// Mitsubishi GX Works2 project: 28.开根指令   PLC: FX3U/FX3UC

PROGRAM MAIN
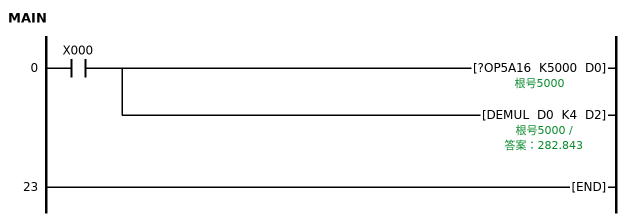
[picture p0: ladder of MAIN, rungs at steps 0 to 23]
0     LD      X000
      ?OP5A16 K5000 D0  ; 根号5000
        [note] 浮点运算加DE。SQR开平方根
      DEMUL   D0 K4 D2  ; 答案：282.843
        [note] 浮点运算加DE
23    END
END_PROGRAM
